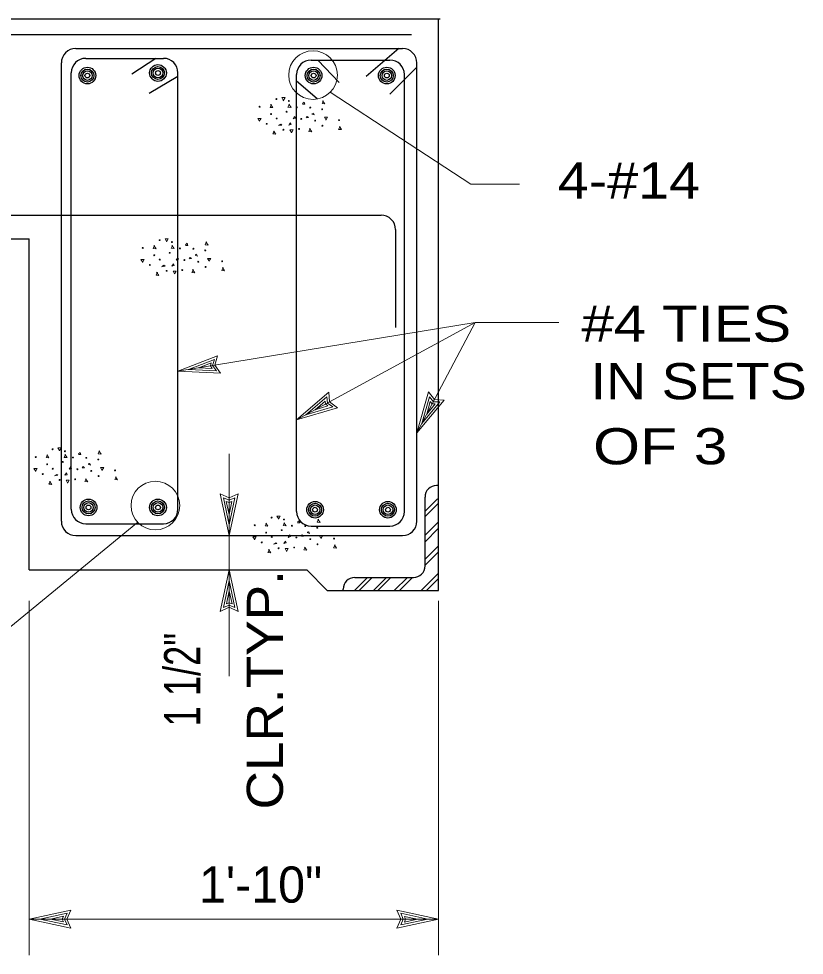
# Model space of a CAD drawing. Extents: x -28.1 to 13.9, y -16.1 to 13.9.
# Drawn here: x -22.028 to -19.312, y -12.795 to -9.557 of the extents above; entities that cross this region are included whole.
import ezdxf
from ezdxf.enums import TextEntityAlignment as Align

# ---------------------------------------------------------------- set-up
doc = ezdxf.new("R2010")
doc.units = 0
doc.header["$LTSCALE"] = 0.05
doc.layers.add('1', color=7, linetype='Continuous', lineweight=13)
doc.layers.add('2', color=7, linetype='Continuous', lineweight=13)

msp = doc.modelspace()

# ---------------------------------------------------------------- linework, layer by layer
at = {"layer": '1', "lineweight": 25}
for p, q in [((-23.82428, -9.55684), (-20.57028, -9.55684)), ((-20.57628, -11.53384), (-20.57628, -9.55684)), ((-23.82428, -9.61184), (-20.67028, -9.61184)), ((-21.83028, -9.65984), (-20.70128, -9.65984)), ((-20.71428, -9.65984), (-20.82628, -9.75684)), ((-21.88028, -11.29384), (-21.88028, -9.70984)), ((-21.79628, -9.69384), (-21.52728, -9.69384)), ((-21.55428, -9.69384), (-21.63628, -9.74884)), ((-21.01728, -9.69984), (-20.74428, -9.69984)), ((-20.99428, -9.69984), (-20.92028, -9.77684)), ((-20.65128, -11.29384), (-20.65128, -9.70984)), ((-21.84628, -11.25284), (-21.84628, -9.74384)), ((-21.47728, -11.25284), (-21.47728, -9.74384)), ((-20.65128, -9.72384), (-20.74428, -9.81784)), ((-21.47728, -9.75684), (-21.57728, -9.81484)), ((-21.06728, -11.26084), (-21.06728, -9.74984)), ((-21.06728, -9.77184), (-20.99628, -9.83284)), ((-20.69428, -11.26084), (-20.69428, -9.74984)), ((-23.81828, -10.23584), (-20.77528, -10.23584)), ((-20.72528, -10.28584), (-20.72528, -10.62384)), ((-23.82528, -10.31784), (-21.99128, -10.31784)), ((-21.99128, -11.46184), (-21.99128, -10.31784)), ((-20.57728, -11.17084), (-20.58328, -11.17084)), ((-20.62328, -11.44884), (-20.62328, -11.21084)), ((-21.79628, -11.30284), (-21.52728, -11.30284)), ((-21.01728, -11.31084), (-20.74428, -11.31084)), ((-21.83028, -11.34384), (-20.70128, -11.34384)), ((-21.99128, -11.46184), (-21.03128, -11.46184)), ((-21.03128, -11.46184), (-20.96128, -11.53384)), ((-20.86628, -11.48884), (-20.66328, -11.48884)), ((-20.96128, -11.53384), (-20.57628, -11.53384)), ((-20.90628, -11.53384), (-20.90628, -11.52884))]:
    msp.add_line(p, q, dxfattribs=at)
at = {"layer": '1'}
for p, q in [((-21.47728, -10.77584), (-20.45028, -10.60684)), ((-21.06728, -10.94384), (-20.45028, -10.60684)), ((-21.47728, -10.77584), (-21.34028, -10.72184)), ((-21.44028, -10.76984), (-21.35128, -10.73484)), ((-21.40528, -10.76384), (-21.36228, -10.74684)), ((-21.36228, -10.74684), (-21.36528, -10.75684)), ((-21.35128, -10.73484), (-21.35728, -10.75584)), ((-21.47728, -10.77584), (-21.33028, -10.78284)), ((-21.44028, -10.76984), (-21.34428, -10.77384)), ((-21.40528, -10.76384), (-21.35928, -10.76584)), ((-21.36528, -10.75684), (-21.35928, -10.76584)), ((-21.35728, -10.75584), (-21.34428, -10.77384)), ((-20.65128, -10.98884), (-20.61128, -10.84684)), ((-21.06728, -10.94384), (-20.95528, -10.84784)), ((-21.03528, -10.92584), (-20.96228, -10.86384)), ((-21.00328, -10.90884), (-20.96828, -10.87884)), ((-20.96828, -10.87884), (-20.96728, -10.88884)), ((-20.96228, -10.86384), (-20.96028, -10.88584)), ((-20.65128, -10.98884), (-20.55728, -10.87584)), ((-20.63428, -10.95584), (-20.60828, -10.86384)), ((-20.60828, -10.86384), (-20.59428, -10.88084)), ((-21.06728, -10.94384), (-20.92628, -10.90184)), ((-21.03528, -10.92584), (-20.94228, -10.89884)), ((-21.00328, -10.90884), (-20.95928, -10.89484)), ((-20.96728, -10.88884), (-20.95928, -10.89484)), ((-20.96028, -10.88584), (-20.94228, -10.89884)), ((-20.63428, -10.95584), (-20.57228, -10.88184)), ((-20.61728, -10.92384), (-20.60528, -10.87984)), ((-20.61728, -10.92384), (-20.58828, -10.88884)), ((-20.60528, -10.87984), (-20.59828, -10.88784)), ((-20.59828, -10.88784), (-20.58828, -10.88884)), ((-20.59428, -10.88084), (-20.57228, -10.88184)), ((-21.30028, -11.34384), (-21.33128, -11.19984)), ((-21.30028, -11.34384), (-21.26928, -11.19984)), ((-21.30028, -11.30684), (-21.32028, -11.21284)), ((-21.32028, -11.21284), (-21.30028, -11.22184)), ((-21.30028, -11.27084), (-21.31028, -11.22584)), ((-21.31028, -11.22584), (-21.30028, -11.22984)), ((-21.30028, -11.30684), (-21.28028, -11.21284)), ((-21.30028, -11.22184), (-21.28028, -11.21284)), ((-21.30028, -11.27084), (-21.29128, -11.22584)), ((-21.30028, -11.22984), (-21.29128, -11.22584)), ((-20.62428, -11.26084), (-20.58028, -11.21684)), ((-20.62128, -11.27684), (-20.57728, -11.23284)), ((-20.62328, -11.34284), (-20.57928, -11.29884)), ((-20.62328, -11.36584), (-20.57728, -11.31984)), ((-20.62328, -11.42584), (-20.57928, -11.38184)), ((-20.62328, -11.44584), (-20.57928, -11.40184)), ((-21.30028, -11.46184), (-21.33128, -11.60584)), ((-21.30028, -11.46184), (-21.26928, -11.60584)), ((-20.86728, -11.53384), (-20.82328, -11.48984)), ((-20.85128, -11.53384), (-20.80728, -11.48984)), ((-20.80128, -11.53384), (-20.75728, -11.48984)), ((-20.78628, -11.53384), (-20.74228, -11.48984)), ((-20.72828, -11.53284), (-20.68428, -11.48884)), ((-20.71128, -11.53384), (-20.66728, -11.48984)), ((-20.63528, -11.53284), (-20.57628, -11.47384)), ((-20.61828, -11.53384), (-20.57628, -11.49184)), ((-21.30028, -11.49884), (-21.32028, -11.59284)), ((-21.30028, -11.49884), (-21.28028, -11.59284)), ((-21.30028, -11.53484), (-21.30928, -11.57984)), ((-21.30028, -11.53484), (-21.29028, -11.57984)), ((-21.99128, -11.56984), (-21.99128, -12.79484)), ((-21.30028, -11.58384), (-21.32028, -11.59284)), ((-21.30028, -11.57584), (-21.30928, -11.57984)), ((-21.29028, -11.57984), (-21.30028, -11.57584)), ((-21.28028, -11.59284), (-21.30028, -11.58384)), ((-20.57628, -11.56984), (-20.57628, -12.79484)), ((-21.99128, -12.66984), (-21.84728, -12.63884)), ((-21.95428, -12.66984), (-21.86028, -12.64984)), ((-21.91828, -12.66984), (-21.87328, -12.65984)), ((-21.87328, -12.65984), (-21.87728, -12.66984)), ((-21.86028, -12.64984), (-21.86928, -12.66984)), ((-20.57628, -12.66984), (-20.72028, -12.63884)), ((-20.61328, -12.66984), (-20.70728, -12.64984)), ((-20.69828, -12.66984), (-20.70728, -12.64984)), ((-21.99128, -12.66984), (-20.57628, -12.66984)), ((-21.99128, -12.66984), (-21.84728, -12.70084)), ((-21.95428, -12.66984), (-21.86028, -12.68984)), ((-21.91828, -12.66984), (-21.87328, -12.67884)), ((-21.87728, -12.66984), (-21.87328, -12.67884)), ((-21.86928, -12.66984), (-21.86028, -12.68984)), ((-20.57628, -12.66984), (-20.72028, -12.70084)), ((-20.61328, -12.66984), (-20.70728, -12.68984)), ((-20.70728, -12.68984), (-20.69828, -12.66984)), ((-20.64928, -12.66984), (-20.69428, -12.66084)), ((-20.69028, -12.66984), (-20.69428, -12.66084)), ((-20.64928, -12.66984), (-20.69428, -12.67984)), ((-20.69428, -12.67984), (-20.69028, -12.66984))]:
    msp.add_line(p, q, dxfattribs=at)
for points in [[(-20.95128, -9.81084), (-20.46528, -10.12884), (-20.29628, -10.12884)], [(-20.65128, -10.98884), (-20.45028, -10.60684), (-20.16017, -10.60684)], [(-21.34028, -10.72184), (-21.34928, -10.75484), (-21.33028, -10.78284)], [(-20.61128, -10.84684), (-20.59028, -10.87384), (-20.55728, -10.87584)], [(-20.95528, -10.84784), (-20.95328, -10.88184), (-20.92628, -10.90184)], [(-21.30028, -11.82984), (-21.30028, -11.46184), (-21.30028, -11.34384), (-21.30028, -11.06084)], [(-21.33128, -11.19984), (-21.30028, -11.21384), (-21.26928, -11.19984)], [(-21.61628, -11.29784), (-22.52128, -12.04084), (-22.75028, -12.04084)], [(-21.26928, -11.60584), (-21.30028, -11.59184), (-21.33128, -11.60584)], [(-21.84728, -12.63884), (-21.86128, -12.66984), (-21.84728, -12.70084)], [(-20.72028, -12.70084), (-20.70628, -12.66984), (-20.72028, -12.63884)]]:
    msp.add_lwpolyline(points, dxfattribs=at)
for centre in [(-21.01028, -9.75184), (-21.55528, -11.23984)]:
    msp.add_circle(centre, 0.0841, dxfattribs=at)
at = {"layer": '1', "lineweight": 25}
for centre, radius in [((-21.79034, -9.75341), 0.02891), ((-21.79034, -9.75341), 0.02242), ((-21.79034, -9.75341), 0.01644), ((-21.79034, -9.75341), 0.0083), ((-21.54634, -9.74441), 0.02891), ((-21.54634, -9.74441), 0.02242), ((-21.54634, -9.74441), 0.01644), ((-21.54634, -9.74441), 0.0083), ((-21.00834, -9.75341), 0.02891), ((-21.00834, -9.75341), 0.02242), ((-21.00834, -9.75341), 0.01644), ((-21.00834, -9.75341), 0.0083), ((-20.75534, -9.75341), 0.02891), ((-20.75534, -9.75341), 0.02242), ((-20.75534, -9.75341), 0.01644), ((-20.75534, -9.75341), 0.0083), ((-21.78634, -11.24641), 0.02891), ((-21.78634, -11.24641), 0.02242), ((-21.78634, -11.24641), 0.01644), ((-21.54634, -11.24641), 0.02891), ((-21.54634, -11.24641), 0.02242), ((-21.54634, -11.24641), 0.01644), ((-21.00334, -11.25441), 0.02891), ((-21.00334, -11.25441), 0.02242), ((-20.75134, -11.25441), 0.02891), ((-20.75134, -11.25441), 0.02242), ((-21.78634, -11.24641), 0.0083), ((-21.54634, -11.24641), 0.0083), ((-21.00334, -11.25441), 0.01644), ((-21.00334, -11.25441), 0.0083), ((-20.75134, -11.25441), 0.01644), ((-20.75134, -11.25441), 0.0083)]:
    msp.add_circle(centre, radius, dxfattribs=at)
for centre, radius, start, end in [((-21.83028, -9.70984), 0.05, 90, 180), ((-20.70128, -9.70984), 0.05, 0, 90), ((-21.79628, -9.74384), 0.05, 90, 180), ((-21.52728, -9.74384), 0.05, 0, 90), ((-21.01728, -9.74984), 0.05, 90, 180), ((-20.74428, -9.74984), 0.05, 0, 90), ((-20.77528, -10.28584), 0.05, 0, 90), ((-20.58328, -11.21084), 0.04, 90, 180), ((-21.79628, -11.25284), 0.05, 180, 270), ((-21.52728, -11.25284), 0.05, 270, 0), ((-21.01728, -11.26084), 0.05, 180, 270), ((-20.74428, -11.26084), 0.05, 270, 0), ((-21.83028, -11.29384), 0.05, 180, 270), ((-20.70128, -11.29384), 0.05, 270, 0), ((-20.66328, -11.44884), 0.04, 270, 0), ((-20.86628, -11.52884), 0.04, 90, 180)]:
    msp.add_arc(centre, radius, start, end, dxfattribs=at)
at = {"layer": '2'}
for p, q in [((-21.04704, -9.85031), (-21.04104, -9.84531)), ((-21.45104, -10.33831), (-21.44504, -10.33331)), ((-21.82104, -11.06131), (-21.81504, -11.05631)), ((-21.06404, -11.29731), (-21.05804, -11.29231))]:
    msp.add_line(p, q, dxfattribs=at)
for points in [[(-21.11304, -9.83831), (-21.11804, -9.82931), (-21.10704, -9.82931), (-21.11304, -9.84031)], [(-20.97404, -9.84031), (-20.97904, -9.85031), (-20.96904, -9.85131), (-20.97704, -9.84031)], [(-21.15404, -9.85331), (-21.15904, -9.86331), (-21.14904, -9.86431), (-21.15704, -9.85331)], [(-21.09204, -9.85231), (-21.09704, -9.86231), (-21.08604, -9.86331), (-21.09404, -9.85231)], [(-21.04104, -9.84531), (-21.03904, -9.85231), (-21.04704, -9.85231)], [(-21.19604, -9.90931), (-21.20104, -9.90131), (-21.19004, -9.90131), (-21.19604, -9.91131)], [(-21.03404, -9.89831), (-21.03104, -9.89431), (-21.02604, -9.89831), (-21.03304, -9.89931)], [(-21.01404, -9.88531), (-21.00904, -9.88331), (-21.00604, -9.88931), (-21.01404, -9.88631)], [(-20.96604, -9.90531), (-20.97104, -9.89731), (-20.96004, -9.89731), (-20.96604, -9.90731)], [(-21.12704, -9.92431), (-21.12204, -9.92131), (-21.11804, -9.92431), (-21.13004, -9.92631)], [(-21.02004, -9.93631), (-21.02504, -9.94631), (-21.01504, -9.94731), (-21.02304, -9.93631)], [(-20.91704, -9.92931), (-20.92204, -9.93931), (-20.91204, -9.94031), (-20.91904, -9.92931)], [(-21.14404, -9.94531), (-21.14904, -9.95531), (-21.13904, -9.95631), (-21.14704, -9.94531)], [(-21.08504, -9.95031), (-21.09004, -9.94131), (-21.07904, -9.94131), (-21.08504, -9.95131)], [(-21.51704, -10.32631), (-21.52204, -10.31731), (-21.51104, -10.31731), (-21.51704, -10.32831)], [(-21.37804, -10.32831), (-21.38304, -10.33831), (-21.37304, -10.33931), (-21.38104, -10.32831)], [(-21.55804, -10.34131), (-21.56304, -10.35131), (-21.55304, -10.35231), (-21.56104, -10.34131)], [(-21.49604, -10.34031), (-21.50104, -10.35031), (-21.49004, -10.35131), (-21.49804, -10.34031)], [(-21.44504, -10.33331), (-21.44304, -10.34031), (-21.45104, -10.34031)], [(-21.60004, -10.39731), (-21.60504, -10.38931), (-21.59404, -10.38931), (-21.60004, -10.39931)], [(-21.43804, -10.38631), (-21.43504, -10.38231), (-21.43004, -10.38631), (-21.43704, -10.38731)], [(-21.41804, -10.37331), (-21.41304, -10.37131), (-21.41004, -10.37731), (-21.41804, -10.37431)], [(-21.37004, -10.39331), (-21.37504, -10.38531), (-21.36404, -10.38531), (-21.37004, -10.39531)], [(-21.53104, -10.41231), (-21.52604, -10.40931), (-21.52204, -10.41231), (-21.53404, -10.41431)], [(-21.42404, -10.42431), (-21.42904, -10.43431), (-21.41904, -10.43531), (-21.42704, -10.42431)], [(-21.32104, -10.41731), (-21.32604, -10.42731), (-21.31604, -10.42831), (-21.32304, -10.41731)], [(-21.54804, -10.43331), (-21.55304, -10.44331), (-21.54304, -10.44431), (-21.55104, -10.43331)], [(-21.48904, -10.43831), (-21.49404, -10.42931), (-21.48304, -10.42931), (-21.48904, -10.43931)], [(-21.88704, -11.04931), (-21.89204, -11.04031), (-21.88104, -11.04031), (-21.88704, -11.05131)], [(-21.92804, -11.06431), (-21.93304, -11.07431), (-21.92304, -11.07531), (-21.93104, -11.06431)], [(-21.86604, -11.06331), (-21.87104, -11.07331), (-21.86004, -11.07431), (-21.86804, -11.06331)], [(-21.81504, -11.05631), (-21.81304, -11.06331), (-21.82104, -11.06331)], [(-21.74804, -11.05131), (-21.75304, -11.06131), (-21.74304, -11.06231), (-21.75104, -11.05131)], [(-21.80804, -11.10931), (-21.80504, -11.10531), (-21.80004, -11.10931), (-21.80704, -11.11031)], [(-21.78804, -11.09631), (-21.78304, -11.09431), (-21.78004, -11.10031), (-21.78804, -11.09731)], [(-21.97004, -11.12031), (-21.97504, -11.11231), (-21.96404, -11.11231), (-21.97004, -11.12231)], [(-21.90104, -11.13531), (-21.89604, -11.13231), (-21.89204, -11.13531), (-21.90404, -11.13731)], [(-21.74004, -11.11631), (-21.74504, -11.10831), (-21.73404, -11.10831), (-21.74004, -11.11831)], [(-21.91804, -11.15631), (-21.92304, -11.16631), (-21.91304, -11.16731), (-21.92104, -11.15631)], [(-21.85904, -11.16131), (-21.86404, -11.15231), (-21.85304, -11.15231), (-21.85904, -11.16231)], [(-21.79404, -11.14731), (-21.79904, -11.15731), (-21.78904, -11.15831), (-21.79704, -11.14731)], [(-21.69104, -11.14031), (-21.69604, -11.15031), (-21.68604, -11.15131), (-21.69304, -11.14031)], [(-21.17104, -11.30031), (-21.17604, -11.31031), (-21.16604, -11.31131), (-21.17404, -11.30031)], [(-21.13004, -11.28531), (-21.13504, -11.27631), (-21.12404, -11.27631), (-21.13004, -11.28731)], [(-21.10904, -11.29931), (-21.11404, -11.30931), (-21.10304, -11.31031), (-21.11104, -11.29931)], [(-21.05804, -11.29231), (-21.05604, -11.29931), (-21.06404, -11.29931)], [(-20.99104, -11.28731), (-20.99604, -11.29731), (-20.98604, -11.29831), (-20.99404, -11.28731)], [(-21.03104, -11.33231), (-21.02604, -11.33031), (-21.02304, -11.33631), (-21.03104, -11.33331)], [(-21.21304, -11.35631), (-21.21804, -11.34831), (-21.20704, -11.34831), (-21.21304, -11.35831)], [(-21.05104, -11.34531), (-21.04804, -11.34131), (-21.04304, -11.34531), (-21.05004, -11.34631)], [(-20.98304, -11.35231), (-20.98804, -11.34431), (-20.97704, -11.34431), (-20.98304, -11.35431)], [(-21.16104, -11.39231), (-21.16604, -11.40231), (-21.15604, -11.40331), (-21.16404, -11.39231)], [(-21.14404, -11.37131), (-21.13904, -11.36831), (-21.13504, -11.37131), (-21.14704, -11.37331)], [(-21.10204, -11.39731), (-21.10704, -11.38831), (-21.09604, -11.38831), (-21.10204, -11.39831)], [(-21.03704, -11.38331), (-21.04204, -11.39331), (-21.03204, -11.39431), (-21.04004, -11.38331)], [(-20.93404, -11.37631), (-20.93904, -11.38631), (-20.92904, -11.38731), (-20.93604, -11.37631)]]:
    msp.add_lwpolyline(points, dxfattribs=at)
for points in [[(-21.07904, -9.90331), (-21.07404, -9.89431), (-21.07104, -9.90031)], [(-21.09404, -9.92431), (-21.08904, -9.91631), (-21.08604, -9.92231)], [(-21.48304, -10.39131), (-21.47804, -10.38231), (-21.47504, -10.38831)], [(-21.49804, -10.41231), (-21.49304, -10.40431), (-21.49004, -10.41031)], [(-21.85304, -11.11431), (-21.84804, -11.10531), (-21.84504, -11.11131)], [(-21.86804, -11.13531), (-21.86304, -11.12731), (-21.86004, -11.13331)], [(-21.11104, -11.37131), (-21.10604, -11.36331), (-21.10304, -11.36931)], [(-21.09604, -11.35031), (-21.09104, -11.34131), (-21.08804, -11.34731)]]:
    msp.add_lwpolyline(points, close=True, dxfattribs=at)
for centre in [(-21.13679, -9.83444), (-21.09404, -9.84119), (-21.19504, -9.86119), (-21.06629, -9.86294), (-21.02004, -9.86394), (-20.97879, -9.86969), (-21.15529, -9.88644), (-21.13604, -9.90169), (-21.10154, -9.87819), (-21.05104, -9.90344), (-21.00304, -9.90919), (-20.92054, -9.90744), (-21.17054, -9.92019), (-21.11254, -9.94044), (-21.05854, -9.93794), (-20.97779, -9.92694), (-21.54079, -10.32244), (-21.49804, -10.32919), (-21.59904, -10.34919), (-21.47029, -10.35094), (-21.42404, -10.35194), (-21.38279, -10.35769), (-21.55929, -10.37444), (-21.54004, -10.38969), (-21.50554, -10.36619), (-21.45504, -10.39144), (-21.32454, -10.39544), (-21.57454, -10.40819), (-21.46254, -10.42594), (-21.40704, -10.39719), (-21.38179, -10.41494), (-21.51654, -10.42844), (-21.96904, -11.07219), (-21.91079, -11.04544), (-21.86804, -11.05219), (-21.84029, -11.07394), (-21.79404, -11.07494), (-21.92929, -11.09744), (-21.87554, -11.08919), (-21.75279, -11.08069), (-21.94454, -11.13119), (-21.91004, -11.11269), (-21.82504, -11.11444), (-21.77704, -11.12019), (-21.75179, -11.13794), (-21.69454, -11.11844), (-21.88654, -11.15144), (-21.83254, -11.14894), (-21.15379, -11.28144), (-21.11104, -11.28819), (-21.21204, -11.30819), (-21.17229, -11.33344), (-21.11854, -11.32519), (-21.08329, -11.30994), (-21.03704, -11.31094), (-20.99579, -11.31669), (-21.15304, -11.34869), (-21.06804, -11.35044), (-21.02004, -11.35619), (-20.93754, -11.35444), (-21.18754, -11.36719), (-21.12954, -11.38744), (-21.07554, -11.38494), (-20.99479, -11.37394)]:
    msp.add_circle(centre, 0.00162, dxfattribs=at)

# ---------------------------------------------------------------- texts
at = {"layer": '1', "width": 1.15}
msp.add_text('4-#14', height=0.125, dxfattribs=at).set_placement((-20.16428, -10.17884))
at = {"layer": '1'}
for s, width, p in [('#4 TIES', 1.2, (-19.71989, -10.67343)), ('IN SETS', 1.15, (-19.67726, -10.87248)), ('OF 3', 1.25, (-19.81012, -11.09745))]:
    msp.add_text(s, height=0.125, dxfattribs=dict(at, width=width)).set_placement(p, align=Align.CENTER)
at = {"layer": '1', "width": 1.1}
msp.add_text('CLR.TYP.', height=0.125, rotation=90, dxfattribs=at).set_placement((-21.11428, -11.87705), align=Align.CENTER)
at = {"layer": '1', "width": 0.75}
msp.add_text('1 1/2"', height=0.125, rotation=90, dxfattribs=at).set_placement((-21.40028, -11.68011), align=Align.RIGHT)
at = {"layer": '1'}
msp.add_text('1\'-10"', height=0.125, dxfattribs=at).set_placement((-21.19157, -12.61284), align=Align.CENTER)

doc.saveas('drawing.dxf')
